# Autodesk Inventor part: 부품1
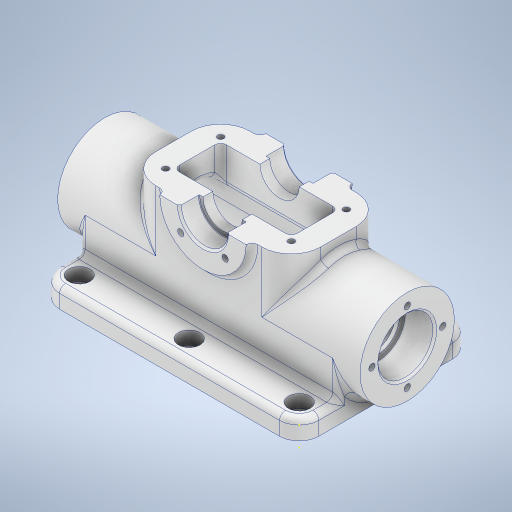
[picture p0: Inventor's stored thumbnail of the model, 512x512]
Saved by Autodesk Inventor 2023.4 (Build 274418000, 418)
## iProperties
Created: 2024-06
Part Number: 부품1
Material: 알루미늄 6061
Document SubType Name: Modeling
Designer: EDU-001
Density: 2.7 g/cm^3
Appearance: 알루미늄 - 평지
Author: EDU-001
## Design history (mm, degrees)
sketch "스케치1"
  geometry: L1 (0, 0)-(132, 0); L2 (132, 0)-(132, -88); L3 (132, -88)-(0, -88); L4 (0, -88)-(0, 0)
  constraints: 8 end point, 2 parallel, 1 horizontal, 1 perpendicular
  dimensions: "d0" = 88 distance of L1.end L2.end; "d1" = 132 distance of L2.end L3.end
extrude "돌출1" new body sketch "스케치1" distance "d2" = 10; taper "d3" = 0 deg
sketch "스케치2"
  geometry: L1 (0, 0)-(88, 0) reference; C1 r 24 at (44, 28); 1 further point
  constraints: 1 centre point, 1 midpoint, 1 vertical alignment
  dimensions: "d4" = 48 diameter of C1; "d5" = 28 distance from line of L1 C1.centre
extrude "돌출2" join sketch "스케치2" distance "d6" = 11; taper "d8" = 0 deg; dims "d7" = 143, "d9" = 0
sketch "스케치3"
  geometry: 1 further point
sketch "스케치4"
  geometry: L1 (20, 28)-(20, -4.738); L2 (68, 28)-(68, -11.168); L3 (0, 10)-(28.125, 10) reference; L4 (59.875, 10)-(88, 10) reference; A1 r 24 centre (44, 28) between (20, 28) and (68, 28) reference; 3 further points
  constraints: 4 end point, 2 point on circle, 2 tangent, 2 vertical
extrude "돌출3" join sketch "스케치4" stored distance "d10" = 11; taper "d11" = 0 deg
sketch "스케치5"
  geometry: 1 further point
sketch "스케치6"
  geometry: L1 (132, 18)-(0, 18) reference; L2 (24, 18)-(108, 18); L3 (108, 18)-(108, 49); L4 (108, 49)-(24, 49); L5 (24, 49)-(24, 18); L6 (0, -10)-(132, -10) reference; 3 further points
  constraints: 8 end point, 2 midpoint, 2 parallel, 1 horizontal, 1 perpendicular, 1 point on line, 1 vertical alignment
  dimensions: "d12" = 84 distance of L3.end L4.end; "d14" = 59 distance between parallel lines of L6 L4
extrude "돌출4" join sketch "스케치6" stored distance "d15" = 10; taper "d16" = 0 deg
node "작업 평면1"
sketch "스케치7"
  geometry: L1 (18, 0)-(18, -28); L2 (-18, 0)-(-18, -28); L3 (-44, -28)-(44, -28) reference; A1 r 18 centre (0, 0) between (18, 0) and (-18, 0); 1 further point
  constraints: 4 end point, 2 point on circle, 2 tangent, 2 vertical, 1 centre point, 1 midpoint, 1 point on line, 1 vertical alignment
  dimensions: "d17" = 36 distance between parallel lines of L1 L2; "d18" = 28 distance from line of L3 A1.centre
extrude "돌출5" cut sketch "스케치7" stored distance "d19" = 120; taper "d20" = 0 deg
sketch "스케치8"
  geometry: L1 (72, -36)-(12, -36); L2 (12, -36)-(12, -12); L3 (12, -12)-(72, -12); L4 (72, -12)-(72, -36); L5 (0, -48)-(84, -48) reference; L6 (0, 0)-(0, -48) reference; 1 further point
  constraints: 8 end point, 2 parallel, 1 horizontal, 1 perpendicular
  dimensions: "d21" = 24 distance between parallel lines of L1 L3; "d22" = 12 distance between parallel lines of L5 L1; "d23" = 60 distance of L1.start L1.end; "d24" = 12 distance between parallel lines of L6 L2
extrude "돌출6" cut sketch "스케치8" extent not by distance; stored distance "d25" = 120; taper "d26" = 0 deg
sketch "스케치9"
  geometry: L1 (108, 49)-(24, 49) reference; C1 r 12 at (66, 49); C2 r 10 at (66, 49); C3 r 22 at (66, 49); 6 further points
  constraints: 4 coincident, 3 centre point, 1 midpoint
  dimensions: "d27" = 24 diameter of C1; "d28" = 20 diameter of C2; "d29" = 44 diameter of C3
extrude "돌출7" join sketch "스케치9" distance "d30" = 3; taper "d31" = 0 deg
sketch "스케치10"
  geometry: L1 (108, 49)-(24, 49) reference; C1 r 12 at (66, 49); C2 r 10 at (66, 49); 1 further point
  constraints: 2 centre point, 1 coincident, 1 midpoint
  dimensions: "d32" = 20 diameter of C2
extrude "돌출8" cut sketch "스케치10" extent not by distance; stored distance "d33" = 0; taper "d34" = 0 deg
extrude "돌출9" cut sketch "스케치10" distance "d35" = 10; taper "d36" = 0 deg
node "작업 평면2"
sketch "스케치11"
  geometry: 1 further point
sketch "스케치12"
  geometry: L1 (-11, 52)-(-11, 4) reference; L2 (-11, 28)-(143, 28); L3 (143, 4)-(143, 52) reference; L4 (-11, 42)-(4, 42); L5 (4, 42)-(4, 39); L6 (4, 39)-(6, 39); L7 (6, 46)-(6, 28) reference; 2 further points
  constraints: 8 end point, 3 midpoint, 2 perpendicular, 2 point on line, 1 horizontal
  dimensions: "d37" = 15 distance of L4.start L4.end; "d38" = 14 distance between parallel lines of L2 L4; "d40" = 11 distance from line of L2 point (5, 39)
revolve "회전1" sketch "스케치12" stored, may be unused: angle "d41" = 90 deg
node "작업 평면3"
sketch "스케치13"
  geometry: A1 r 18 centre (0, 0) between (12, 13.416) and (-12, 13.416); A2 r 18 centre (0, 0) between (12, 13.416) and (-12, 13.416) reference; A3 r 18 centre (0, 0) between (18, 0) and (-18, 0) reference; 4 further points
  constraints: 2 point on circle, 1 centre point, 1 coincident
  dimensions: "d42" = 36 diameter of A1
hole "구멍1" sketch "스케치13" at (0, 18), (18, 0), (0, -18), (-18, 0) diameter "d43" = 3.242; stored, may be unused: countersink angle "d47" = 90 deg, drill point angle "d49" = 118 deg; dims "d44" = 8, "d45" = 4, "d46" = 2, "d48" = 10
fillet "모깎기1" dims "d50" = 10
fillet "모깎기2" dims "d51" = 3
fillet "모깎기3" dims "d52" = 15
fillet "모깎기4" dims "d53" = 3
fillet "모깎기5" dims "d54" = 3
fillet "모깎기6" dims "d55" = 3
sketch "스케치14"
  geometry: 1 further point
sketch "스케치15"
  geometry: L1 (-78, 17)-(-54, 17) reference; L2 (-78, 71)-(-54, 71) reference; A1 r 7 centre (-122, 10) between (-129, 10) and (-122, 3) reference; A2 r 7 centre (-122, 78) between (-122, 85) and (-129, 78) reference; A3 r 10 centre (-10, 10) between (-10, 0) and (0, 10) reference; A4 r 7 centre (-10, 78) between (-3, 78) and (-10, 85) reference; 9 further points
  constraints: 4 coincident, 2 horizontal alignment, 2 midpoint, 2 vertical alignment
hole "구멍2" sketch "스케치15" at (-122, 10), (-122, 78), (-10, 10), (-10, 78), (-66, 78), (-66, 10) diameter "d56" = 6.6; stored, may be unused: countersink angle "d60" = 90 deg, drill point angle "d62" = 118 deg; dims "d57" = 8, "d58" = 11, "d59" = 6.6, "d61" = 10
fillet "모깎기7" dims "d63" = 3
fillet "모깎기8" dims "d64" = 3
chamfer "모따기1" distance "d65" = 1; stored, may be unused: second distance "d66" = 2, angle "d67" = 45 deg
sketch "스케치16"
  geometry: L1 (-42, -31)-(22, -31); L2 (22, -31)-(22, -3); L3 (22, -3)-(-42, -3); L4 (-42, -3)-(-42, -31); L5 (0, -5)-(-20, -5) reference; L6 (20, -8)-(20, -26) reference; 9 further points
  constraints: 8 end point, 4 coincident, 4 midpoint, 2 parallel, 1 horizontal, 1 horizontal alignment, 1 perpendicular, 1 vertical alignment
  dimensions: "d68" = 28 distance of L1.end L2.end; "d69" = 64 distance of L2.end L3.end
hole "구멍3" sketch "스케치16" at (-42, -3), (-42, -31), (22, -31), (22, -3) diameter "d70" = 3.242; stored, may be unused: countersink angle "d74" = 90 deg, drill point angle "d76" = 118 deg; dims "d71" = 8, "d72" = 11, "d73" = 6.6, "d75" = 10
chamfer "모따기2" distance "d77" = 1; stored, may be unused: second distance "d78" = 2, angle "d79" = 45 deg
fillet "모깎기9" dims "d80" = 0.3
sketch "스케치17"
  geometry: L1 (66, 49)-(66, 32.697); L2 (93, 32.697)-(39, 32.697) reference; L3 (54.686, 37.686)-(66, 49); L4 (66, 49)-(77.314, 37.686); A1 r 12 centre (66, 49) between (54, 49) and (78, 49) reference; A2 r 16 centre (66, 49) between (54.686, 37.686) and (77.314, 37.686); 1 further point
  constraints: 6 end point, 2 point on circle, 1 centre point, 1 coincident, 1 midpoint, 1 perpendicular
  dimensions: "d81" = 32 diameter of A2; "d82" = 45 deg angle of L1 L3
hole "구멍4" sketch "스케치17" at (54.686, 37.686), (77.314, 37.686) diameter "d83" = 3.242; stored, may be unused: countersink angle "d87" = 90 deg, drill point angle "d89" = 118 deg; dims "d84" = 8, "d85" = 4, "d86" = 2, "d88" = 10
sketch "스케치18"
  geometry: L1 (48.309, -6.285)-(77.691, -6.285); L2 (77.691, -6.285)-(77.691, -9.715); L3 (77.691, -9.715)-(48.309, -9.715); L4 (48.309, -9.715)-(48.309, -6.285); L5 (7, -28)-(119, -28) reference; A1 r 13 centre (63, 31) between (50, 31) and (76, 31) reference; 4 further points
  constraints: 2 midpoint, 1 point on circle, 1 vertical alignment, 2 other
  dimensions: "d90" = 20 distance from line of L5 point (77.691, -8)
feature "엠보싱1" sketch "스케치18" dims "d91" = 0.5, "d92" = 0
node "솔리드1"
mirror "미러1"
mirror "미러2"
mirror "미러3"
mirror "미러4"
feature "A9D066F2-1C7D-4E18-AEED-F7BC21143FA4" dims "d56" = 6.6, "d57" = 8, "d58" = 11, "d59" = 6.6, "d60" = 90 deg, "d61" = 10, "d62" = 118 deg
